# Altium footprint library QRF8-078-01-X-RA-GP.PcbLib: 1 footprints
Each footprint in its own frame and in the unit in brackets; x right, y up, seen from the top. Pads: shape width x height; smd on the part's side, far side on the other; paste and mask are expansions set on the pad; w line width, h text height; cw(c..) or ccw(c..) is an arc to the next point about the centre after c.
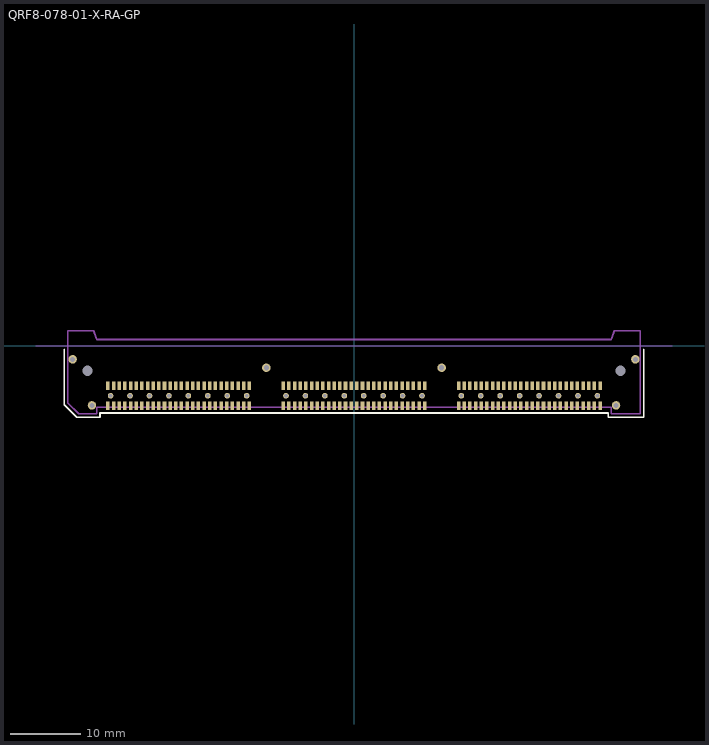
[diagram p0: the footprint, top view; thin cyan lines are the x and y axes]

## QRF8-078-01-X-RA-GP [mm]
pads (188):
  rect 0.5x1.25 smd mask+0.05: 1(-34.8,-8.5) 2(-34.8,-5.67) 3(-34,-8.5) 4(-34,-5.67) 5(-33.2,-8.5) 6(-33.2,-5.67) 7(-32.4,-8.5) 8(-32.4,-5.67) 9(-31.6,-8.5) 10(-31.6,-5.67) 11(-30.8,-8.5) 12(-30.8,-5.67) 13(-30,-8.5) 14(-30,-5.67) 15(-29.2,-8.5) 16(-29.2,-5.67) 17(-28.4,-8.5) 18(-28.4,-5.67) 19(-27.6,-8.5) 20(-27.6,-5.67) 21(-26.8,-8.5) 22(-26.8,-5.67) 23(-26,-8.5) 24(-26,-5.67) 25(-25.2,-8.5) 26(-25.2,-5.67) 27(-24.4,-8.5) 28(-24.4,-5.67) 29(-23.6,-8.5) 30(-23.6,-5.67) 31(-22.8,-8.5) 32(-22.8,-5.67) 33(-22,-8.5) 34(-22,-5.67) 35(-21.2,-8.5) 36(-21.2,-5.67) 37(-20.4,-8.5) 38(-20.4,-5.67) 39(-19.6,-8.5) 40(-19.6,-5.67) 41(-18.8,-8.5) 42(-18.8,-5.67) 43(-18,-8.5) 44(-18,-5.67) 45(-17.2,-8.5) 46(-17.2,-5.67) 47(-16.4,-8.5) 48(-16.4,-5.67) 49(-15.6,-8.5) 50(-15.6,-5.67) 51(-14.8,-8.5) 52(-14.8,-5.67) 53(-10,-8.5) 54(-10,-5.67) 55(-9.2,-8.5) 56(-9.2,-5.67) 57(-8.4,-8.5) 58(-8.4,-5.67) 59(-7.6,-8.5) 60(-7.6,-5.67) 61(-6.8,-8.5) 62(-6.8,-5.67) 63(-6,-8.5) 64(-6,-5.67) 65(-5.2,-8.5) 66(-5.2,-5.67) 67(-4.4,-8.5) 68(-4.4,-5.67) 69(-3.6,-8.5) 70(-3.6,-5.67) 71(-2.8,-8.5) 72(-2.8,-5.67) 73(-2,-8.5) 74(-2,-5.67) 75(-1.2,-8.5) 76(-1.2,-5.67) 77(-0.4,-8.5) 78(-0.4,-5.67) 79(0.4,-8.5) 80(0.4,-5.67) 81(1.2,-8.5) 82(1.2,-5.67) 83(2,-8.5) 84(2,-5.67) 85(2.8,-8.5) 86(2.8,-5.67) 87(3.6,-8.5) 88(3.6,-5.67) 89(4.4,-8.5) 90(4.4,-5.67) 91(5.2,-8.5) 92(5.2,-5.67) 93(6,-8.5) 94(6,-5.67) 95(6.8,-8.5) 96(6.8,-5.67) 97(7.6,-8.5) 98(7.6,-5.67) 99(8.4,-8.5) 100(8.4,-5.67) 101(9.2,-8.5) 102(9.2,-5.67) 103(10,-8.5) 104(10,-5.67) 105(14.8,-8.5) 106(14.8,-5.67) 107(15.6,-8.5) 108(15.6,-5.67) 109(16.4,-8.5) 110(16.4,-5.67) 111(17.2,-8.5) 112(17.2,-5.67) 113(18,-8.5) 114(18,-5.67) 115(18.8,-8.5) 116(18.8,-5.67) 117(19.6,-8.5) 118(19.6,-5.67) 119(20.4,-8.5) 120(20.4,-5.67) 121(21.2,-8.5) 122(21.2,-5.67) 123(22,-8.5) 124(22,-5.67) 125(22.8,-8.5) 126(22.8,-5.67) 127(23.6,-8.5) 128(23.6,-5.67) 129(24.4,-8.5) 130(24.4,-5.67) 131(25.2,-8.5) 132(25.2,-5.67) 133(26,-8.5) 134(26,-5.67) 135(26.8,-8.5) 136(26.8,-5.67) 137(27.6,-8.5) 138(27.6,-5.67) 139(28.4,-8.5) 140(28.4,-5.67) 141(29.2,-8.5) 142(29.2,-5.67) 143(30,-8.5) 144(30,-5.67) 145(30.8,-8.5) 146(30.8,-5.67) 147(31.6,-8.5) 148(31.6,-5.67) 149(32.4,-8.5) 150(32.4,-5.67) 151(33.2,-8.5) 152(33.2,-5.67) 153(34,-8.5) 154(34,-5.67) 155(34.8,-8.5) 156(34.8,-5.67)
  round 0.8 hole 0.53 mask+0.075: 157(-34.425,-7.08) 158(-31.675,-7.08) 159(-28.925,-7.08) 160(-26.175,-7.08) 161(-23.425,-7.08) 162(-20.675,-7.08) 163(-17.925,-7.08) 164(-15.175,-7.08) 165(-9.625,-7.08) 166(-6.875,-7.08) 167(-4.125,-7.08) 168(-1.375,-7.08) 169(1.375,-7.08) 170(4.125,-7.08) 171(6.875,-7.08) 172(9.625,-7.08) 173(15.175,-7.08) 174(17.925,-7.08) 175(20.675,-7.08) 176(23.425,-7.08) 177(26.175,-7.08) 178(28.925,-7.08) 179(31.675,-7.08) 180(34.425,-7.08)
  round 1.2 hole 0.71 mask+0.075: 181(-39.8,-1.93) 182(-37.06,-8.44) 183(-12.4,-3.12) 184(12.4,-3.12) 185(39.8,-1.93) 186(37.06,-8.44)
  round 0 hole 1.45 unplated: 187(-37.7,-3.56) 188(37.7,-3.56)
Top Overlay:
  lines w0.254: -40.975,-0.5 -40.975,-8.358 -39.203,-10.13 -35.93,-10.13 -35.93,-9.5 35.95,-9.5 35.95,-10.13 40.975,-10.13 40.975,-0.5
Mechanical 1:
  lines w0.254: -40.475,-8.11 -38.955,-9.63 -36.375,-9.63 -36.375,-8.7 36.375,-8.7 36.375,-9.63 40.475,-9.63 40.475,2.12 36.835,2.12 36.38,0.87 -36.38,0.87 -36.835,2.12 -40.475,2.12 -40.475,-8.11
  text "J1" at -0.446,-2.994 h0.76
Mechanical 16:
  lines w0.01: -45,0 45,0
